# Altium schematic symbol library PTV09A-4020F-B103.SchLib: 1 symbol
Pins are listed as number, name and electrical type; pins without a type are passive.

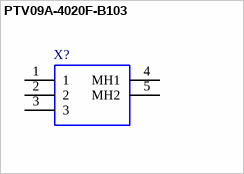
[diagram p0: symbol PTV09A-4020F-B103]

## PTV09A-4020F-B103
designator X?
9mm carbon potentiometer linear 10K 20% Bourns PTV Series, Linear Potentiometer with a 6 mm Dia. Shaft, 10k, +/-20%, 0.05W, Through Hole; Geometry.Height: 20mm
footprint PTV09A4020FB103
pins: 1, 2, 3, 4 MH1, 5 MH2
